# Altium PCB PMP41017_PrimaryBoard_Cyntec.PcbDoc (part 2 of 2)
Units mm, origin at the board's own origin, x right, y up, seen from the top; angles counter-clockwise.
Board outline 81.79 x 50.02 mm, 4 copper layers (Top Layer, Layer 2, Layer 3, Bottom Layer), stack 1.194 mm thick; 52 components, 42 nets, 218 pads, 652 vias.
Unrouted connection lines stored in the file: 2.
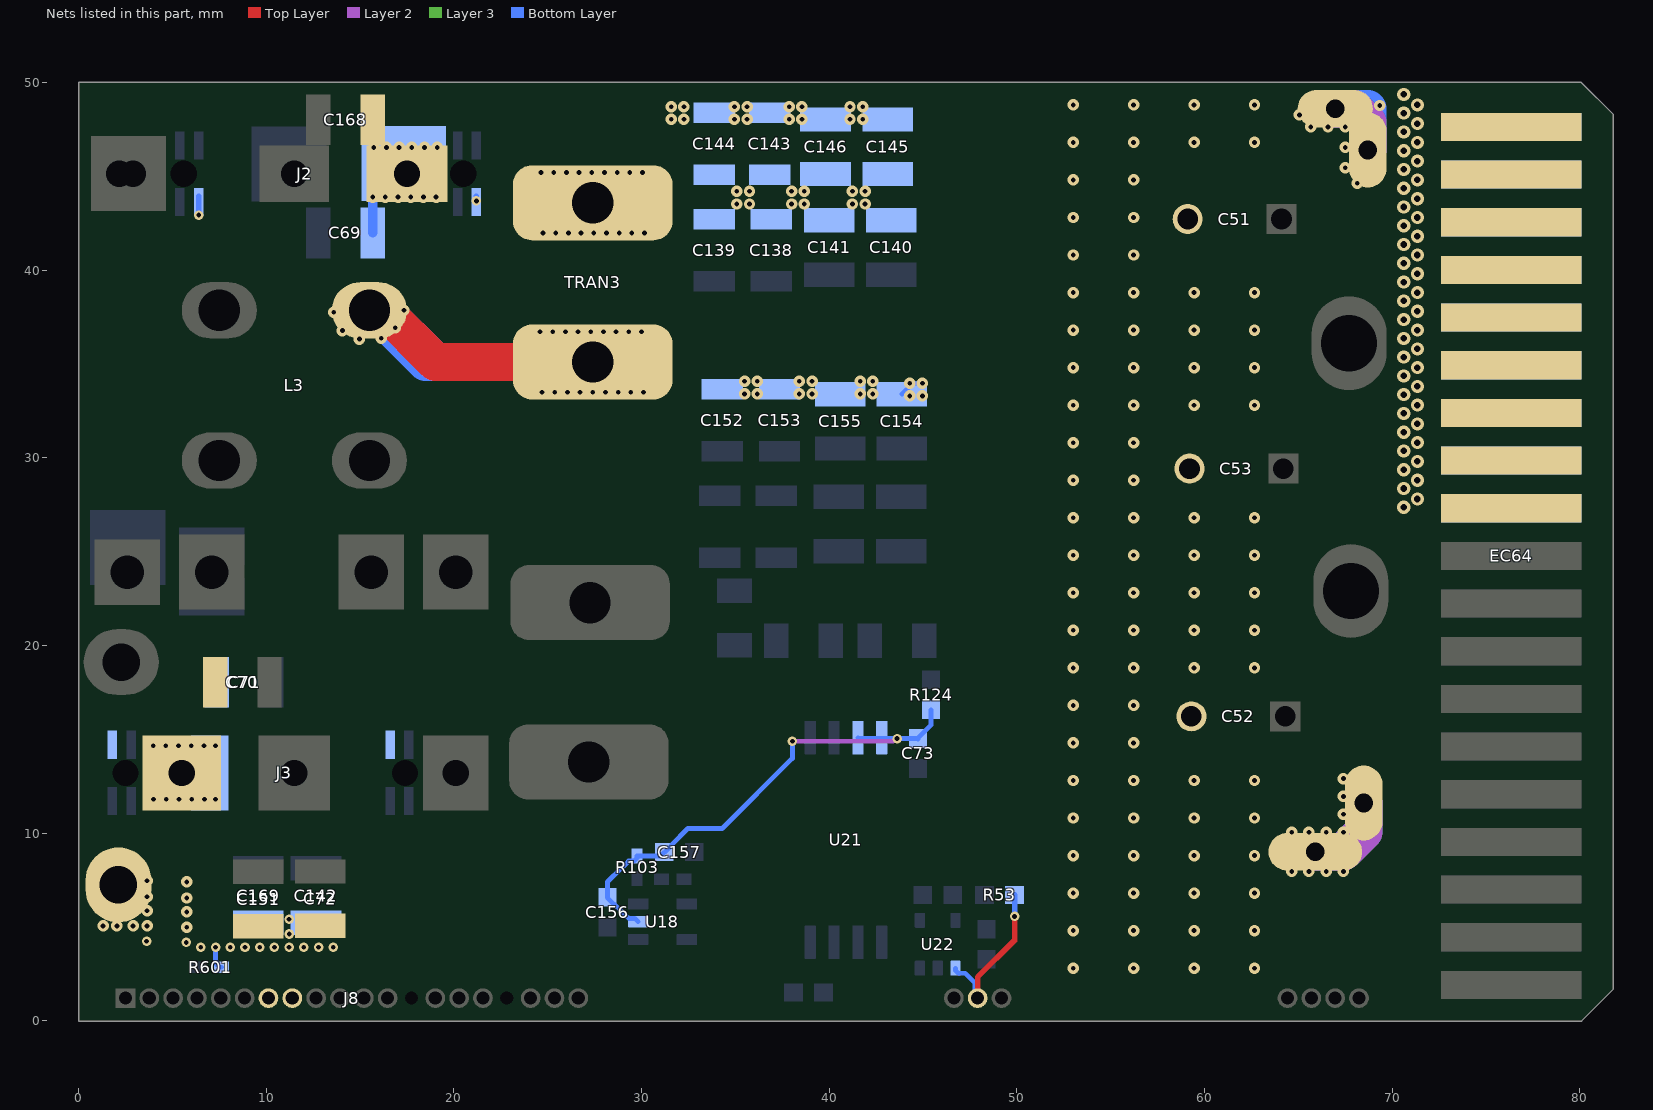
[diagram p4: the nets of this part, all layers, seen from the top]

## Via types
v1: diameter 0.61, hole 0.254, Top Layer to Bottom Layer, tented both sides, 497 vias
v2: diameter 0.7, hole 0.35, Top Layer to Bottom Layer, tented both sides, 110 vias
v3: diameter 0.508, hole 0.254, Top Layer to Bottom Layer, tented both sides, 45 vias

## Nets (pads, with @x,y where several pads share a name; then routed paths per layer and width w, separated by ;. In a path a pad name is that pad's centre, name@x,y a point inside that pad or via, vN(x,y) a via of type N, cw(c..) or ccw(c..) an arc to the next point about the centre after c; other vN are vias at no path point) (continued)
PB_PGND: C69.2 C70.2 C71.2 C72.2 C73.2 C142.2 C143.2 C144.2 C145.2 C146.2 C151.2 C152.2 C153.2 C154.2 C155.2 C156.2 C157.2 C168.2 C169.2 J2.PG J3.PG pad.5@2.126,7.238 pad.5@6.985,13.2 pad.5@17.321,45.681 R103.1 R124.1 R601.1 U18.2 U21.3 U21.4 | length 32.6
  Layer 2 w0.254: v3(38.038,14.891) 43.407,14.891 43.548,15.031 v3(43.616,15.031)
  Bottom Layer w0.254: v3(7.301,3.914) 7.301,3.169 7.351,3.119 7.351,3.019 7.524,2.846 R601.1@7.624,2.846 ; C69.2@15.673,41.978 C69.2@15.674,41.977 ; U18.2@29.815,5.274 29.642,5.447 29.314,5.447 29.167,5.594 29.158,5.594 28.935,5.817 28.935,5.826 28.556,6.205 28.531,6.205 28.183,6.553 C156.2@28.183,6.578 28.183,7.378 ; v3(38.038,14.891) 38.038,13.975 34.304,10.241 32.474,10.241 31.587,9.354 31.587,9.329 31.239,8.981 C157.2@31.214,8.981 31.008,8.776 R103.1@29.759,8.776 29.759,8.676 29.586,8.503 29.307,8.503 28.556,7.751 ; U21.3@41.529,15.082 41.57,15.041 v3@43.616,15.041 ; v3(43.616,15.031) 44.722,15.031 44.737,15.016 C73.2@44.737,15.041 44.737,15.066 45.429,15.758 R124.1@45.429,16.57 ; C154.2@43.873,33.391 44.452,33.969 v1(44.969,33.969) ; 28.183,7.378 28.556,7.751 ; 28.183,7.378 28.183,7.403 28.531,7.751 28.556,7.751
  Bottom Layer w0.5: C69.2@15.673,41.978 v1(15.673,43.885)
  Bottom Layer w2: pad.5@2.126,7.238 pad.5@2.126,7.508
  other v1: 5.77,4.984 1.305,5.05 2.045,5.05 2.903,5.05 3.65,5.05 5.77,5.798 3.65,5.865 5.77,6.539 3.65,6.605 5.77,7.397 3.65,7.463 4,11.798 4.676,11.798 5.352,11.798 6.028,11.798 6.704,11.798 7.295,11.798 3.974,14.65 4.651,14.65 5.327,14.65 6.003,14.65 6.679,14.65 7.295,14.65 44.292,33.293 44.969,33.293 35.489,33.399 36.165,33.399 38.409,33.399 39.085,33.399 41.647,33.399 42.323,33.399 44.292,33.969 35.489,34.075 36.165,34.075 38.409,34.075 39.085,34.075 41.647,34.075 42.323,34.075 16.349,43.885 17.025,43.885 17.701,43.885 18.377,43.885 19.053,43.885 15.728,46.535 16.404,46.535 17.08,46.535 17.757,46.535 18.433,46.535 19.109,46.535 31.582,48.028 32.258,48.028 34.948,48.028 35.625,48.028 37.868,48.028 38.544,48.028 41.107,48.028 41.783,48.028 31.582,48.704 32.258,48.704 34.948,48.704 35.625,48.704 37.868,48.704 38.544,48.704 41.107,48.704 41.783,48.704
  other v3: 6.517,3.914 8.084,3.914 8.868,3.914 9.652,3.914 10.436,3.914 11.22,3.914 12.003,3.914 12.787,3.914 13.571,3.914 5.742,4.168 3.622,4.234 11.232,4.619 11.22,5.403
PB_RX-PFC: J8.8
PB_TX-PFC: J8.7
TEMP_1H_1: J2.5 | length 1
  Bottom Layer w0.3: v3(6.4,42.926) J2.5@6.4,43.933
TEMP_1L_1: J2.1 | length 0.3
  Bottom Layer w0.3: v3(21.2,43.683) J2.1@21.2,43.933
TEMP_2H_1: J3.5
TEMP_2L_1: J3.1
TR1_HV_N: C138.2 C139.2 C140.2 C141.2 C143.1 C144.1 C145.1 C146.1 TRAN3.2 | length 4.2
  Top Layer w2: TRAN3.2@27.4,43.58 TRAN3.2@27.727,43.907
  Layer 2 w2: TRAN3.2@27.4,43.58 TRAN3.2@27.727,43.907
  Layer 3 w2: TRAN3.2@27.4,43.58 TRAN3.2@27.727,43.907
  Bottom Layer w2: TRAN3.2@27.4,43.58 TRAN3.2@30.191,43.58
  other v1: 24.749,41.969 25.425,41.969 26.101,41.969 26.777,41.969 27.454,41.969 28.13,41.969 28.806,41.969 29.482,41.969 30.158,41.969 35.075,43.52 35.752,43.52 37.995,43.52 38.672,43.52 41.234,43.52 41.91,43.52 35.075,44.196 35.752,44.196 37.995,44.196 38.672,44.196 41.234,44.196 41.91,44.196 24.642,45.191 25.318,45.191 25.994,45.191 26.67,45.191 27.346,45.191 28.023,45.191 28.699,45.191 29.375,45.191 30.051,45.191
TR1_HV_P: L3.1 TRAN3.1 | length 37.6
  Top Layer w2: L3.1@15.5,37.852 16.271,37.852 19.023,35.1 TRAN3.1@27.4,35.1
  Layer 2 w2: L3.1@15.5,37.852 16.271,37.852 19.023,35.1 TRAN3.1@27.4,35.1
  Bottom Layer w2: L3.1@16.654,36.941 18.495,35.1 TRAN3.1@27.4,35.1
  other v1: 24.696,33.489 25.372,33.489 26.048,33.489 26.724,33.489 27.4,33.489 28.076,33.489 28.753,33.489 29.429,33.489 30.105,33.489 14.967,36.319 16.128,36.36 24.588,36.711 25.264,36.711 25.94,36.711 26.616,36.711 27.293,36.711 27.969,36.711 28.645,36.711 29.321,36.711 29.997,36.711 14.058,36.774 16.875,36.92 13.6,37.746 17.339,37.852
V0-out: C51.2 C52.2 C53.2 EC64.A1 EC64.A2 EC64.A3 EC64.A4 EC64.A5 EC64.A6 EC64.A7 EC64.A8 EC64.A9 EC64.B1 EC64.B2 EC64.B3 EC64.B4 EC64.B5 EC64.B6 EC64.B7 EC64.B8 EC64.B9 pad.4@65.9,9 pad.4@66.963,48.6 pad.4@68.7,46.4 pad.4@68.481,11.6 | length 16.5
  Layer 2 w2: pad.4@65.9,9 67.4,9 68.481,10.081 pad.4@68.481,11.6 ; pad.4@66.963,48.6 67.963,48.6 68.7,47.863 pad.4@68.7,46.4
  Bottom Layer w2: pad.4@65.9,9 67.4,9 68.481,10.081 pad.4@68.481,11.6 ; pad.4@66.963,48.6 68.7,48.6 pad.4@68.7,46.4
  other v1: 53,2.8 56.22,2.8 59.44,2.8 62.66,2.8 53,4.8 56.22,4.8 59.44,4.8 62.66,4.8 53,6.8 56.22,6.8 59.44,6.8 62.66,6.8 64.643,7.954 65.562,7.954 66.481,7.954 67.4,7.954 53,8.8 56.22,8.8 59.44,8.8 62.66,8.8 64.643,10.046 65.562,10.046 66.481,10.046 67.4,10.046 53,10.8 56.22,10.8 59.44,10.8 62.66,10.8 67.4,10.997 67.4,11.948 53,12.8 56.22,12.8 59.44,12.8 62.66,12.8 67.4,12.899 53,14.8 56.22,14.8 53,16.8 56.22,16.8 53,18.8 56.22,18.8 59.44,18.8 62.66,18.8 53,20.8 56.22,20.8 59.44,20.8 62.66,20.8 53,22.8 56.22,22.8 59.44,22.8 62.66,22.8 53,24.8 56.22,24.8 59.44,24.8 62.66,24.8 53,26.8 56.22,26.8 59.44,26.8 62.66,26.8 53,28.8 56.22,28.8 53,30.8 56.22,30.8 53,32.8 56.22,32.8 59.44,32.8 62.66,32.8 53,34.8 56.22,34.8 59.44,34.8 62.66,34.8 53,36.8 56.22,36.8 59.44,36.8 62.66,36.8 53,38.8 56.22,38.8 59.44,38.8 62.66,38.8 53,40.8 56.22,40.8 53,42.8 56.22,42.8 68.131,44.63 53,44.8 56.22,44.8 67.497,45.447 67.497,46.536 53,46.8 56.22,46.8 59.44,46.8 62.66,46.8 65.659,47.625 66.578,47.625 67.497,47.625 65.054,48.263 69.332,48.768 53,48.8 56.22,48.8 59.44,48.8 62.66,48.8
  other v2: 70.612,27.359 71.341,27.8 70.612,28.359 71.341,28.8 70.612,29.359 71.341,29.8 70.612,30.359 71.341,30.8 70.612,31.359 71.341,31.8 70.612,32.359 71.341,32.8 70.612,33.359 71.341,33.8 70.612,34.359 71.341,34.8 70.612,35.359 71.341,35.8 70.612,36.359 71.341,36.8 70.612,37.359 71.341,37.8 70.612,38.359 71.341,38.8 70.612,39.359 71.341,39.8 70.612,40.359 71.341,40.8 70.612,41.359 71.341,41.8 70.612,42.359 71.341,42.8 70.612,43.359 71.341,43.8 70.612,44.359 71.341,44.8 70.612,45.359 71.341,45.8 70.612,46.359 71.341,46.8 70.612,47.359 71.341,47.8 70.612,48.359 71.341,48.8 70.612,49.359
VPRI: pad.5@47.91,1.2 R53.1 U22.1 | length 8.6
  Top Layer w0.3: pad.5@47.91,1.2 47.91,2.319 49.878,4.287 v3(49.878,5.554)
  Bottom Layer w0.254: U22.1@46.731,2.799 46.731,2.674 46.879,2.526 47.242,2.526 47.758,2.01 47.758,1.352 pad.5@47.91,1.2
  Bottom Layer w0.3: v3(49.878,5.554) R53.1@49.878,6.701
pads on no net: EC64.A19 EC64.B19 J2.0 J3.0 J8.2 J8.3 J8.13 J8.17

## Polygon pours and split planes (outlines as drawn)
no net on Bottom Layer "BOTTOM_LAYER_NONET_P078" (solid, remove dead copper, pour order 78): 42.54,5.077 42.54,3.525 43.659,2.406 47.212,2.406 47.212,5.735 46.963,5.984 43.447,5.984
12Vout on Bottom Layer "Bottom Layer-12Vout" (solid, remove dead copper, pour order 64): 51.816,49.53 51.816,2.794 53.34,1.27 65.435,1.27 70.196,1.27 72.574,3.648 80.088,3.648 80.088,25.514 70.965,25.514 69.43,27.049 69.43,41.817 61.717,49.53
V0-out on Bottom Layer "BOTTOM_LAYER_V0-OUT_P077" (solid, remove dead copper, pour order 77): 63.305,9.714 67.295,13.705 69.518,13.705 69.723,13.5 69.723,9.049 68.032,7.359 64.081,7.359 63.305,8.135
CT2_P on Bottom Layer "BOTTOM_LAYER_CT2_P_P076" (solid, remove dead copper, pour order 76): 18.373,26 31.673,26 31.673,19.836 20.144,19.836 18.373,21.607
CT1_N on Bottom Layer "BOTTOM_LAYER_CT1_N_P067" (solid, remove dead copper, pour order 67): 8.12,35.174 9.775,36.83 9.775,38.662 8.55,39.887 8.534,39.87 5.207,39.87 5.207,35.772 5.805,35.174
V0-out on Bottom Layer "BOTTOM_LAYER_V0-OUT_P059" (solid, remove dead copper, pour order 59): 70.156,41.951 70.156,27.295 70.93,26.522 80.088,26.522 80.088,48.359 72.545,48.359 71.12,49.784 64.516,49.784 64.516,47.654 70.112,42.058
GaN2_SW on Bottom Layer "BOTTOM_LAYER_GAN2_SW_P001" (solid, remove dead copper, pour order 1): 18.669,10.16 27.498,10.16 29.291,11.953 30.755,11.953 31.673,12.87 31.673,16.206 31.115,16.764 23.44,16.764 22.57,15.895 18.373,15.895 18.373,10.456
HVBUS on Bottom Layer "BOTTOM_LAYER_HVBUS_P055" (solid, remove dead copper, pour order 55): 0.011,20.927 4.424,20.927 4.424,18.554 2.983,17.113 0.127,17.113
TR1_HV_P on Bottom Layer "BOTTOM_LAYER_TR1_HV_P_P051" (solid, remove dead copper, pour order 51): 13.247,38.504 14.121,39.378 17.556,39.378 19.473,37.461 30.531,37.461 31.673,36.319 31.673,33.788 30.967,33.083 17.046,33.083 13.247,36.882
TR1_HV_N on Bottom Layer "BOTTOM_LAYER_TR1_HV_N_P031" (solid, remove dead copper, pour order 31): 23.168,45.104 24.022,45.958 44.974,45.958 45.696,45.236 45.696,42.662 44.718,41.684 23.951,41.684 23.16,42.475
HVBUS on Bottom Layer "BOTTOM_LAYER_HVBUS_P045" (solid, remove dead copper, pour order 45): 9.054,49.059 9.652,49.657 13.52,49.657 13.52,43.141 13.172,42.793 9.443,42.793 9.054,43.182
PB_PGND on Bottom Layer "Bottom Layer-PB_GND_D" (solid, remove dead copper, pour order 44): 0.154,5.05 1.923,3.281 14.242,3.281 14.242,5.942 7.405,5.942 6.604,6.743 6.604,9.667 7.93,10.992 7.93,18.923 6.731,18.923 3.683,15.875 3.492,15.684 3.492,10.946 2.313,9.767 0.154,9.767
HVBUS on Bottom Layer "BOTTOM_LAYER_HVBUS_P034" (solid, remove dead copper, pour order 34): 9.578,18.415 10.886,18.415 13.335,15.966 13.335,7.463 9.578,7.463
HVBUS on Bottom Layer "BOTTOM_LAYER_HVBUS_P033" (solid, remove dead copper, pour order 33): 33.581,25.786 45.657,25.786 45.657,23.35 33.746,23.35 33.162,23.935 33.162,25.367
PB_PGND on Bottom Layer "BOTTOM_LAYER_PB_PGND_P032" (solid, remove dead copper, pour order 32): 45.325,32.64 33.127,32.64 33.127,35.076 45.159,35.076 45.743,34.491 45.743,33.059
HVBUS on Bottom Layer "BOTTOM_LAYER_HVBUS_P030" (solid, remove dead copper, pour order 30): 33.058,40.513 45.593,40.513 45.72,40.386 45.72,38.541 45.256,38.077 33.224,38.077 32.639,38.662 32.639,40.094
NetC147_2 on Bottom Layer "BOTTOM_LAYER_NETC147_2_P029" (solid, remove dead copper, pour order 29): 13.579,30.689 14.654,31.764 44.509,31.764 45.642,30.63 45.642,27.825 44.869,27.051 15.315,27.051 13.535,28.831
PB_PGND on Bottom Layer "BOTTOM_LAYER_PB_PGND_P024" (solid, remove dead copper, pour order 24): 32.258,49.657 44.831,49.657 45.72,48.768 45.72,47.117 20.101,47.117 16.107,43.123 15,43.123 15,49.657
CT1_P on Bottom Layer "BOTTOM_LAYER_CT1_P_P005" (solid, remove dead copper, pour order 5): 0.127,47.879 0.127,22.88 0.762,22.245 4.211,22.245 4.699,22.733 4.699,48.26 0.508,48.26
PB_PGND on Top Layer "TOP_LAYER_PB_PGND_P075" (solid, remove dead copper, pour order 75): 32.258,49.657 44.831,49.657 45.72,48.768 45.72,47.117 20.101,47.117 16.107,43.123 15,43.123 15,49.657
HVBUS on Top Layer "TOP_LAYER_HVBUS_P074" (solid, remove dead copper, pour order 74): 33.581,25.786 45.657,25.786 45.657,23.35 33.746,23.35 33.162,23.935 33.162,25.367
PB_PGND on Top Layer "TOP_LAYER_PB_PGND_P073" (solid, remove dead copper, pour order 73): 45.325,32.64 33.127,32.64 33.127,35.076 45.159,35.076 45.743,34.491 45.743,33.059
HVBUS on Top Layer "TOP_LAYER_HVBUS_P072" (solid, remove dead copper, pour order 72): 33.058,40.513 45.593,40.513 45.72,40.386 45.72,38.541 45.256,38.077 33.224,38.077 32.639,38.662 32.639,40.094
CT1_N on Top Layer "TOP_LAYER_CT1_N_P068" (solid, remove dead copper, pour order 68): 5.207,39.87 8.715,39.87 9.775,38.809 9.775,36.83 8.548,35.603 5.376,35.603 5.207,35.772
V0-out on Top Layer "Top Layer-V0-out" (solid, remove dead copper, pour order 62): 51.816,49.784 51.816,2.794 53.34,1.27 68.58,1.27 69.618,2.308 69.618,13.68 64.624,18.674 64.624,25.046 66.099,26.522 80.088,26.522 80.088,48.359 72.545,48.359 71.12,49.784 65.024,49.784
12Vout on Top Layer "TOP_LAYER_12VOUT_P061" (solid, remove dead copper, pour order 61): 70.062,3.706 70.062,14.368 65.435,18.995 65.435,24.604 66.617,25.786 71.256,25.786 71.529,25.514 80.088,25.514 80.088,3.648 72.574,3.648 72.314,3.388 70.38,3.388
GaN2_SW on Top Layer "TOP_LAYER_GAN2_SW_P057" (solid, remove dead copper, pour order 57): 18.373,10.456 18.373,15.895 22.57,15.895 23.44,16.764 31.115,16.764 31.673,16.206 31.673,11.673 30.16,10.16 18.669,10.16
HVBUS on Top Layer "TOP_LAYER_HVBUS_P054" (solid, remove dead copper, pour order 54): 0.011,20.927 4.424,20.927 4.424,18.554 2.983,17.113 0.127,17.113
CT1_N on Top Layer "TOP_LAYER_CT1_N_P053" (solid, remove dead copper, pour order 53): 5.327,27.012 5.747,27.432 8.146,27.432 9.578,26 9.578,22.297 9.125,21.844 5.327,21.844
TR1_HV_P on Top Layer "TOP_LAYER_TR1_HV_P_P052" (solid, remove dead copper, pour order 52): 13.247,39.368 13.749,39.87 17.064,39.87 19.473,37.461 30.808,37.461 31.673,36.596 31.673,33.788 30.967,33.083 17.046,33.083 13.247,36.882
NetC147_2 on Top Layer "TOP_LAYER_NETC147_2_P028" (solid, remove dead copper, pour order 28): 13.579,30.689 14.654,31.764 44.509,31.764 45.642,30.63 45.642,27.825 44.869,27.051 15.154,27.051 13.531,28.674
PB_PGND on Top Layer "TOP_LAYER_PB_PGND_P046" (solid, remove dead copper, pour order 46): 15,49.657 18.521,49.657 19.668,48.51 19.668,41.684 15.011,41.684
TR1_HV_N on Top Layer "TOP_LAYER_TR1_HV_N_P041" (solid, remove dead copper, pour order 41): 22.912,44.502 24.205,45.795 44.81,45.795 45.429,45.175 45.429,42.396 44.554,41.52 23.787,41.52 22.906,42.402
PB_PGND on Top Layer "Top Layer-PB_GND_D" (solid, remove dead copper, pour order 39): 0.154,5.612 2.484,3.281 14.65,3.281 14.65,5.713 6.907,5.713 6.604,6.016 6.604,9.667 7.93,10.992 7.93,18.923 6.731,18.923 3.683,15.875 3.302,15.494 3.302,10.756 2.313,9.767 0.154,9.767
HVBUS on Top Layer "TOP_LAYER_HVBUS_P035" (solid, remove dead copper, pour order 35): 9.578,18.653 10.648,18.653 13.335,15.966 13.335,7.293 9.578,7.293
CT1_P on Top Layer "TOP_LAYER_CT1_P_P009" (solid, remove dead copper, pour order 9): 0.127,47.879 0.127,22.47 0.489,22.107 4.301,22.107 4.699,22.505 4.699,48.26 0.508,48.26
HVBUS on Top Layer "TOP_LAYER_HVBUS_P007" (solid, remove dead copper, pour order 7): 9.054,49.657 9.054,41.684 13.832,41.684 13.832,49.657
V0-out on Layer 3 "LAYER_3_V0-OUT_P048" (solid, remove dead copper, pour order 48): 52.197,49.784 78.74,49.784 80.088,48.436 80.088,2.54 78.818,1.27 53.34,1.27 52.197,2.413
PB_PGND on Layer 3 "LAYER_3_PB_PGND_P022" (solid, remove dead copper, pour order 22): 11.959,18.653 11.959,25.635 19.185,25.635 19.185,39.721 18.812,40.094 13.813,40.094 13.813,49.657 44.831,49.657 46.99,47.498 46.99,13.73 35.8,2.54 2.808,2.54 0,5.348 0.078,16.3 9.606,16.3
CT1_N on Layer 3 "LAYER_3_CT1_N_P010" (solid, remove dead copper, pour order 10): 0.519,35.726 0.519,21.844 9.125,21.844 9.652,22.371 9.652,27.716 6.414,27.716 5.08,29.049 5.08,32.135 8.548,35.603 9.775,36.83 9.775,38.662 8.55,39.887 4.68,39.887
12Vout on Layer 2 "Layer 2-12Vout" (solid, remove dead copper, pour order 66): 51.816,2.794 53.34,1.27 78.558,1.27 80.088,2.8 80.088,26.522 70.148,26.521 69.723,26.946 69.723,41.975 64.1,47.598 64.1,49.751 61.948,49.75 51.816,49.75
V0-out on Layer 2 "LAYER_2_V0-OUT_P060" (solid, remove dead copper, pour order 60): 64.516,47.783 70.112,42.187 70.156,42.08 70.156,27.015 80.088,27.015 80.088,48.359 78.663,49.784 64.581,49.784 64.516,49.719
HVBUS on Layer 2 "Layer 2-HVBUS" (solid, remove dead copper, pour order 27): 15.093,42.545 25.744,42.545 26.87,41.418 26.943,41.388 45.696,41.388 45.72,41.364 46.99,40.094 46.99,17.907 45.593,16.51 15.416,16.51 14.002,15.097 14.002,10.643 13.52,10.16 10.12,10.16 9.339,10.941 9.339,15.279 8.108,16.51 0.73,16.51 0.127,17.113 0.127,20.193 1.27,21.336 29.241,21.336 30.861,22.956 30.861,36.937 30.206,37.592 13.146,37.592 9.054,41.684 9.054,49.657 14.224,49.657 14.224,43.414
PB_PGND on Layer 2 "LAYER_2_PB_PGND_P018" (solid, remove dead copper, pour order 18): 0.834,4.931 2.706,3.06 14.058,3.06 14.058,8.793 9.628,8.793 7.85,10.55 7.85,15.668 7.643,15.875 3.683,15.875 3.302,15.494 3.302,10.756 2.706,10.16 0.834,10.16
TR1_HV_N on Layer 2 "LAYER_2_TR1_HV_N_P042" (solid, remove dead copper, pour order 42): 23.315,44.905 24.205,45.795 45.335,45.795 45.335,41.52 23.787,41.52 23.306,42.001
PB_PGND on Layer 2 "LAYER_2_PB_PGND_P021" (solid, remove dead copper, pour order 21): 15.093,49.383 15.367,49.657 44.831,49.657 45.593,48.895 45.593,45.958 15.093,45.958
CT1_N on Layer 2 "LAYER_2_CT1_N_P014" (solid, remove dead copper, pour order 14): 0.519,35.628 0.519,21.844 8.602,21.844 9.054,22.295 9.054,27.051 7.078,27.051 5.479,28.65 5.479,32.941 9.775,37.237 9.775,38.662 8.55,39.887 4.778,39.887

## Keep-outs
Keep-Out Layer:
  text ".Layer_Name" at -20.343,-59.464 h1.52

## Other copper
Top Layer:
  rectangle net PB_PGND: 7.267,11.182 7.879,16
  rectangle net 12Vout: 72.574,3.648 80.097,25.479
  rectangle net V0-out: 72.583,26.522 80.095,48.343
  rectangle net GaN2_SW: 21.55,10.357 23.44,15.684
  text ".Layer_Name" at -20.343,-59.464 h1.52
Layer 2:
  rectangle net CT1_P: 0.281,21.844 3.937,26.225
  rectangle net CT1_P: 0.281,42.229 4.604,48.069
  pour cut-out: 19.705,47.061 cw(c20.205,47.061) 20.705,47.061 cw(c20.205,47.061)
Layer 3:
  rectangle net TEMP_1H_1: 6.075,42.333 7.1,43.907
  rectangle net TEMP_1L_1: 20.619,43.275 22,44.184
  rectangle net CT1_P: 0.281,21.844 3.937,26.225
Bottom Layer:
  rectangle net V0-out: 72.583,26.522 80.095,48.343
  rectangle net 12Vout: 72.574,3.648 80.097,25.479
  rectangle net GaN2_SW: 21.55,10.652 23.44,15.684
  rectangle net TEMP_2H_1: 15.416,14.272 16.858,16.51
  rectangle net TEMP_2L_1: 0.445,14.272 2.1,15.78
  pour cut-out: 19.693,47.063 cw(c20.193,47.063) 20.693,47.063 cw(c20.193,47.063)
  text ".Layer_Name" at -20.343,-59.464 h1.52

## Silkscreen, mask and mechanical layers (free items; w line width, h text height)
Top Overlay:
  lines w0.2: 0.005,0 0.005,3.273 32.005,3.273 32.005,0 0.005,0
  text "'.PRJ_Number'.PCB_Rev" at 116.739,-34.38 h2.75
  text ".Layer_Name" at -20.343,-59.464 h1.52
Bottom Overlay:
  text ".Layer_Name" at -20.343,-59.464 h1.52
Top Paste:
  text ".Layer_Name" at -20.343,-59.464 h1.52
Bottom Paste:
  text ".Layer_Name" at -20.343,-59.464 h1.52
Top Solder:
  text ".Layer_Name" at -20.343,-59.464 h1.52
  text ".Layer_Name" at -20.343,-59.464 h1.52
Bottom Solder:
  text ".Layer_Name" at -20.343,-59.464 h1.52
Drill Guide:
  text ".Layer_Name" at -20.343,-59.464 h1.52
M1 Board Outline:
  lines w0.1: 70,50 0,50 0,0 0,-0.017 80.088,-0.017 81.788,1.683 81.788,48.283 80.071,50 70.005,50
  text ".Layer_Name" at -20.343,-59.464 h1.52
M2 Board Dimensions:
  rectangle: -34.999,-44.643 -31.824,-41.468
  rectangle: -31.824,-47.818 -22.299,-44.643
  lines w0.178: -34.999,-44.643 -9.599,-44.643 ; -31.824,-47.818 -31.824,-41.468 ; -28.649,-47.818 -28.649,-41.468 ; -22.299,-47.818 -22.299,-41.468 ; -15.949,-47.818 -15.949,-41.468 ; -34.999,-47.818 -9.599,-47.818 -9.599,-41.468 -34.999,-41.468 -34.999,-47.818
  text ".Layer_Name" at -20.343,-59.464 h1.52
M3 3D STEP Top:
  text ".Layer_Name" at -20.343,-59.464 h1.52
M4 3D STEP Bottom:
  text ".Layer_Name" at -20.343,-59.464 h1.52
M5 Assembly Top:
  lines w0.254: -42.416,-61.285 125.224,-61.285 ; -42.416,-56.12 125.275,-56.12 ; -42.416,-50.955 -42.416,-66.449 59.311,-66.449 125.275,-66.449 125.275,-50.955 -42.403,-50.955 -42.403,-66.449 -2.386,-66.449 ; 20.195,-66.449 20.195,-50.955 ; 52.377,-56.12 52.377,-50.955 ; 73.713,-56.12 73.713,-50.955 ; 89.512,-66.614 89.512,-61.463
  text "COMPONENTS MARKED 'DNP' SHOULD NOT BE POPULATED." at -5.7,-45.748 h1.52
  text "ASSEMBLY VARIANT:" at -5.713,-48.682 h1.52
  text ".VariantName" at 20.601,-48.682 h1.52
  text "PCB VIEWED FROM TOP SIDE" at -40.803,-54.312 h1.52
  text "BOARD #:" at 22.1,-54.312 h1.52
  text ".PRJ_Number" at 35.956,-54.312 h1.52
  text "REV:" at 57.406,-54.312 h1.52
  text ".PCB_Rev" at 64.81,-54.312 h1.52
  text "SVN REV:" at 78.691,-54.312 h1.52
  text ".VersionControl_RevNumber" at 91.544,-54.312 h1.52
  text "TID #:" at 22.1,-59.477 h1.52
  text ".TID" at 35.956,-59.477 h1.52
  text "PLOT NAME =" at -40.803,-64.693 h1.52
  text ".plot_File_Name" at -20.343,-64.693 h1.52
  text "GENERATED    :" at 22.151,-64.693 h1.52
  text ".Print_Date" at 44.236,-64.693 h1.52
  text ".Print_Time" at 62.753,-64.693 h1.52
  text "TEXAS INSTRUMENTS" at 94.871,-64.693 h1.52
M6 Assembly Bottom:
  lines w0.254: -42.429,-56.133 125.262,-56.133 ; -42.378,-61.297 125.262,-61.297 ; -6.665,-66.627 -6.665,-61.475 ; 9.133,-56.133 9.133,-50.968 ; 30.469,-56.133 30.469,-50.968 ; 62.651,-66.462 62.651,-50.968 ; 85.232,-66.462 125.249,-66.462 125.249,-50.968 -42.429,-50.968 -42.429,-66.462 23.535,-66.462 125.262,-66.462 125.262,-50.968
  text "COMPONENTS MARKED 'DNP' SHOULD NOT BE POPULATED." at 119.992,-45.736 h1.52
  text ".VariantName" at 93.474,-48.682 h1.52
  text "ASSEMBLY VARIANT:" at 119.865,-48.682 h1.52
  text ".VersionControl_RevNumber" at -8.697,-54.325 h1.52
  text "SVN REV:" at 4.155,-54.325 h1.52
  text ".PCB_Rev" at 18.036,-54.325 h1.52
  text "REV:" at 25.44,-54.325 h1.52
  text ".PRJ_Number" at 46.89,-54.325 h1.52
  text "BOARD #:" at 60.746,-54.325 h1.52
  text "PCB VIEWED FROM BOTTOM SIDE" at 123.649,-54.325 h1.52
  text ".TID" at 46.89,-59.49 h1.52
  text "TID #:" at 60.746,-59.49 h1.52
  text "TEXAS INSTRUMENTS" at -12.025,-64.705 h1.52
  text ".Print_Time" at 20.093,-64.705 h1.52
  text ".Print_Date" at 38.61,-64.705 h1.52
  text "GENERATED    :" at 60.695,-64.705 h1.52
  text ".plot_File_Name" at 103.19,-64.705 h1.52
  text "PLOT NAME =" at 123.649,-64.705 h1.52
M9 Title Sheet:
  drawing of 57 lines, arcs and shapes, not listed
  text "1" at -16.207,166.469 h1.78
  text "2" at 47.183,166.469 h1.78
  text "3" at 110.412,166.469 h1.78
  text "4" at 174.081,166.469 h1.78
  text "5" at 237.556,166.469 h1.78
  text "6" at 301.183,166.469 h1.78
  text "A" at -45.578,137.436 h1.78
  text "A" at 330.342,137.436 h1.78
  text "B" at -45.578,76.984 h1.78
  text "B" at 330.342,76.984 h1.78
  text "C" at -45.578,16.659 h1.78
  text "C" at 330.342,16.659 h1.78
  text "PROJECT TITLE:" at 253.126,-30.61 h1.14
  text ".PRJ_Title" at 254.396,-33.996 h1.78
  text "DESIGNED FOR:" at 253.126,-38.255 h1.14
  text ".PRJ_Customer" at 254.396,-41.811 h1.78
  text "D" at -45.578,-43.539 h1.78
  text "D" at 330.342,-43.539 h1.78
  text "FILE NAME:" at 253.126,-45.875 h1.14
  text ".PCB_File_Name_No_Path" at 254.396,-48.923 h1.78
  text "Texas Instruments (TI) and/or its licensors do not warrant the accuracy or completeness of this specification" at 126.9,-53.034 h1.14
  text "ENGINEER:" at 253.126,-53.241 h1.14
  text "LAYOUT BY:" at 291.353,-53.241 h1.14
  text "or any information contained therein. TI and/or its licensors do not warrant that this design will meet" at 125.758,-55.896 h1.14
  text ".PRJ_Engineer" at 254.396,-57.178 h1.78
  text ".PCB_Layout" at 292.635,-57.178 h1.78
  text "the specifications, will be suitable for your application or fit for any particular purpose, or will operate in" at 125.758,-58.757 h1.14
  text ".Layer_Name" at -20.343,-59.464 h1.52
  text "ALTIUM DESIGNER VERSION:" at 291.353,-61.115 h1.14
  text "an implementation. TI and/or its licensors do not warrant that the design is production worthy. You should" at 125.758,-61.619 h1.14
  text "completely validate and test your design implementation to confirm the system functionality for your application." at 126.9,-64.481 h1.14
  text ".print_Scale" at 254.396,-64.502 h1.78
  text ".Application_BuildNumber" at 292.635,-64.502 h1.78
  text "1" at -16.207,-69.751 h1.78
  text "2" at 47.183,-69.751 h1.78
  text "3" at 110.412,-69.751 h1.78
  text "4" at 174.081,-69.751 h1.78
  text "5" at 237.556,-69.751 h1.78
  text "6" at 301.183,-69.751 h1.78
M10 Fab Notes:
  drawing of 189 lines, arcs and shapes, not listed
  text "DESIGN INFORMATION" at 279.504,123.788 h1.52
  text "MIN. TRACK WIDTH:" at 263.132,120.432 h1.52
  text "8" at 290.977,120.432 h1.52
  text "MIL" at 294.908,120.432 h1.52
  text "7.874" at 286.751,117.342 h1.52
  text "MIN. CLEARANCE:" at 263.132,117.28 h1.52
  text "MIL" at 294.908,117.28 h1.52
  text "MIN. VIA PAD SIZE:" at 263.132,114.127 h1.52
  text "24" at 290.215,114.127 h1.52
  text "MIL" at 294.908,114.127 h1.52
  text "0.05mm (2MIL)" at 280.785,110.827 h1.52
  text "MINIMUM ANNULAR RING" at 254.77,110.618 h1.52
  text "EXTERNAL" at 298.769,110.618 h1.52
  text "PER" at 259.85,107.821 h1.52
  text "IPC-D-275 CLASS 2 LEVEL C" at 265.438,107.821 h1.52
  text "MIL, HOLES" at 303.239,105.269 h1.52
  text "+/-" at 293.27,105.051 h1.52
  text "+/-" at 314.962,105.051 h1.52
  text "REGISTRATION TOLERANCES:" at 254.77,105.024 h1.52
  text "METAL" at 285.244,105.024 h1.52
  text "5" at 299.88,105.024 h1.52
  text "3" at 321.038,105.024 h1.52
  text "MIL" at 323.991,105.024 h1.52
  text "HOLE SIZE TOLERANCE (UNLESS OTHERWISE SPECIFIED):" at 254.77,102.527 h1.52
  text "+/-" at 314.962,102.454 h1.52
  text "3" at 321.038,102.427 h1.52
  text "MIL" at 323.991,102.427 h1.52
  text "MATERIAL:" at 252.871,98.931 h1.52
  text "FR-4 High Tg" at 277.926,95.666 h1.52
  text "X" at 274.258,95.463 h1.52
  text "FR-408" at 263.564,95.348 h1.52
  text "OTHER" at 301.359,95.348 h1.52
  text "62 MIL (1.6mm) +/-10%" at 271.695,91.715 h1.52
  text "X" at 268.644,91.653 h1.52
  text "THICKNESS:" at 254.77,91.507 h1.52
  text "OTHER" at 304.331,91.507 h1.52
  text "TOLERANCE:" at 254.77,87.993 h1.52
  text "X" at 276.315,87.993 h1.52
  text "ANSI IPC-6012 TYPE 3 CLASS 2" at 280.837,87.993 h1.52
  text "OTHER +/-" at 280.836,84.331 h1.52
  text "BOW & TWIST:" at 254.77,80.643 h1.52
  text "X" at 276.315,80.643 h1.52
  text "ANSI IPC-6012 TYPE 3 CLASS 2" at 280.837,80.643 h1.52
  text "OTHER +/-" at 280.836,76.917 h1.52
  text "DRILLING:" at 252.871,73.599 h1.52
  text "NC_DRILL FILES" at 297.6,70.928 h1.52
  text "REFERENCE:" at 254.77,70.828 h1.52
  text "X" at 271.464,70.825 h1.52
  text "AS SHOWN" at 275.985,70.828 h1.52
  text "X" at 294.349,70.828 h1.52
  text "OTHER" at 305.169,67.214 h1.52
  text "PTH COPPER THICKNESS:" at 254.762,67.125 h1.52
  text "X" at 283.698,67.125 h1.52
  text "20-30 um" at 286.949,67.125 h1.52
  text "BOARD FINISH:" at 252.871,63.376 h1.52
  text "SILKSCREEN:" at 256.813,60.579 h1.52
  text "X" at 281.141,60.579 h1.52
  text "TOP" at 284.113,60.579 h1.52
  text "X" at 294.095,60.579 h1.52
  text "BOTTOM" at 297.092,60.579 h1.52
  text "SILKSCREEN COLOR:" at 256.813,56.637 h1.52
  text "X" at 281.116,56.637 h1.52
  text "WHITE" at 284.113,56.637 h1.52
  text "OTHER" at 297.092,56.637 h1.52
  text "X" at 284.443,52.993 h1.52
  text "GREEN" at 287.44,52.993 h1.52
  text "OTHER" at 303.137,52.993 h1.52
  text "SOLDER RESIST COLOR:" at 256.813,52.819 h1.52
  text "X" at 284.443,49.075 h1.52
  text "MATTE" at 287.44,49.075 h1.52
  text "SEMI-GLOSS" at 303.126,49.059 h1.52
  text "IMMERSION GOLD (ENIG)" at 279.82,44.687 h1.52
  text "ENEPIG" at 313.794,44.503 h1.52
  text "SURFACE FINISH:" at 252.871,44.478 h1.52
  text "X" at 275.299,44.478 h1.52
  text "IMM. TIN/SILVER OR EQUIV" at 261.241,40.99 h1.52
  text "OTHER" at 297.6,40.89 h1.52
  text "ARRAY/PANEL:" at 252.871,36.944 h1.52
  text "CUT AND TRIM PER M1 BOARD OUTLINE" at 279.82,36.735 h1.52
  text "N.C. ROUTE" at 279.82,33.281 h1.52
  text "X" at 297.295,33.281 h1.52
  text "V. SCORE" at 301.817,33.281 h1.52
  text "CERTIFICATION:" at 252.871,30.001 h1.52
  text "MATERIALS AND WORKMANSHIP FOR ALL PCBS" at 271.286,30.001 h1.52
  text "TO MEET OR EXCEED THE REQUIREMENTS OF:" at 271.286,27.612 h1.52
  text "X" at 262.078,24.345 h1.52
  text "ANSI IPC-A-600F CLASS ->" at 265.33,24.345 h1.52
  text "X" at 307.189,24.345 h1.52
  text "2" at 309.983,24.345 h1.52
  text "1" at 301.982,24.307 h1.52
  text "3" at 318.974,24.307 h1.52
  text "X" at 282.703,20.594 h1.52
  text "RoHS" at 285.954,20.594 h1.52
  text "OTHER" at 302.322,20.594 h1.52
  text "PER ORDER" at 312.407,20.594 h1.52
  text "ALL BOARDS MUST MEET OR EXCEED UL94-V0 REQUIREMENTS." at 253.57,16.687 h1.52
  text "PCB MUST BEAR THE UL94V-0 UL REGISTERED MATERIAL ID NUMBER" at 253.57,13.739 h1.52
  text "ADDITIONAL REQUIREMENTS:" at 252.871,9.435 h1.52
  text "MICROSECTION:" at 254.77,6.714 h1.52
  text "YES" at 277.776,6.714 h1.52
  text "REQUIRED" at 299.658,3.048 h1.52
  text "BARE BOARD ELEC. TEST:" at 254.77,2.976 h1.52
  text "NONE" at 287.936,2.976 h1.52
  text "X" at 296.66,2.976 h1.52
  text "PER ORDER" at 314.694,2.976 h1.52
  text "XX MIL VIAS REQUIRE NON-CONDUCTIVE FILL AND PLANARIZE" at 259.041,-2.23 h1.5
  text "XX MIL VIAS REQUIRE CONDUCTIVE FILL AND PLANARIZE" at 259.244,-4.871 h1.52
  text "OUTER XX MIL TRACES REQUIRE 50 OHM SINGLE-ENDED IMPEDANCE" at 259.219,-9.021 h1.47
  text "LAYER 2 & 3 (INNER LAYERS) XX MIL WIDE, XX MIL SPACE / TRACES REQUIRE 100 OHM DIFFERENTIAL IMPEDANCE" at 259.016,-15.008 h1.52
  text ".Layer_Name" at -20.343,-59.464 h1.52
M11 Gerber Information:
  lines w0.254: -42.416,-61.285 125.224,-61.285 ; -42.416,-56.12 125.275,-56.12 ; -42.416,-50.955 -42.416,-66.449 59.311,-66.449 125.275,-66.449 125.275,-50.955 -42.403,-50.955 -42.403,-66.449 -2.386,-66.449 ; 20.195,-66.449 20.195,-50.955 ; 52.377,-56.12 52.377,-50.955 ; 73.713,-56.12 73.713,-50.955 ; 89.512,-66.614 89.512,-61.463
  text "ALL ARTWORK VIEWED FROM TOP SIDE" at -40.803,-54.312 h1.52
  text "BOARD #:" at 22.1,-54.312 h1.52
  text ".PRJ_Number" at 35.956,-54.312 h1.52
  text "REV:" at 57.406,-54.312 h1.52
  text ".PCB_Rev" at 64.81,-54.312 h1.52
  text "SVN REV:" at 78.691,-54.312 h1.52
  text ".VersionControl_RevNumber" at 91.544,-54.312 h1.52
  text "LAYER NAME =" at -40.803,-59.464 h1.52
  text "TID #:" at 22.1,-59.477 h1.52
  text ".TID" at 35.956,-59.477 h1.52
  text "PLOT NAME =" at -40.803,-64.693 h1.52
  text ".plot_File_Name" at -20.343,-64.693 h1.52
  text "GENERATED    :" at 22.151,-64.693 h1.52
  text ".Print_Date" at 44.236,-64.693 h1.52
  text ".Print_Time" at 62.753,-64.693 h1.52
  text "TEXAS INSTRUMENTS" at 94.871,-64.693 h1.52
M12 Stackup:
  drawing of 341 lines, arcs and shapes, not listed
  text "Layer" at 214.469,162.365 h1.52
  text "Name" at 224.881,162.365 h1.52
  text "Material" at 248.497,162.365 h1.52
  text "Thickness" at 270.335,162.365 h1.52
  text "Constant" at 286.841,162.365 h1.52
  text "Board Layer Stack" at 301.315,162.365 h1.52
  text "Top Overlay" at 224.881,159.317 h1.52
  text "Top Solder" at 224.881,156.269 h1.52
  text "Solder Resist" at 248.497,156.269 h1.52
  text "0.40mil" at 270.335,156.269 h1.52
  text "3.5" at 286.841,156.269 h1.52
  text "1" at 214.469,153.221 h1.52
  text "Top Layer" at 224.881,153.221 h1.52
  text "CF-005" at 248.497,153.221 h1.52
  text "2.76mil" at 270.335,153.221 h1.52
  text "Dielectric 1" at 224.881,150.173 h1.52
  text "PP-022" at 248.497,150.173 h1.52
  text "12.00mil" at 270.335,150.173 h1.52
  text "4.5" at 286.841,150.173 h1.52
  text "2" at 214.469,147.125 h1.52
  text "Layer 2" at 224.881,147.125 h1.52
  text "CF-005" at 248.497,147.125 h1.52
  text "2.76mil" at 270.335,147.125 h1.52
  text "Dielectric3" at 224.881,144.077 h1.52
  text "Core-029" at 248.497,144.077 h1.52
  text "12.00mil" at 270.335,144.077 h1.52
  text "4.7" at 286.841,144.077 h1.52
  text "3" at 214.469,141.029 h1.52
  text "Layer 3" at 224.881,141.029 h1.52
  text "CF-005" at 248.497,141.029 h1.52
  text "2.76mil" at 270.335,141.029 h1.52
  text "Dielectric 5" at 224.881,137.981 h1.52
  text "PP-022" at 248.497,137.981 h1.52
  text "12.00mil" at 270.335,137.981 h1.52
  text "4.5" at 286.841,137.981 h1.52
  text "4" at 214.469,134.933 h1.52
  text "Bottom Layer" at 224.881,134.933 h1.52
  text "CF-005" at 248.497,134.933 h1.52
  text "2.76mil" at 270.335,134.933 h1.52
  text "Bottom Solder" at 224.881,131.885 h1.52
  text "Solder Resist" at 248.497,131.885 h1.52
  text "0.40mil" at 270.335,131.885 h1.52
  text "3.5" at 286.841,131.885 h1.52
  text "Bottom Overlay" at 224.881,128.837 h1.52
  text "GaN Board1" at 6.652,47.652 h0.89
  text "Transformer1" at 34.152,38.852 h0.89
  text "Resonant Choke 1&2" at 3.652,33.652 h0.89
  text "Board_CST" at 6.752,20.301 h0.89
  text "Transformer2" at 33.322,17.718 h0.89
  text "GaN Board2" at 7.352,13.952 h0.89
  text "Flyback" at 2.002,3.849 h0.89
  text "McU Board" at 49.452,2.352 h0.89
  text ".Layer_Name" at -20.343,-59.464 h1.52
M13 Component Bodies Top:
  text ".Layer_Name" at -20.343,-59.464 h1.52
M14 Component Bodies Bottom:
  text ".Layer_Name" at -20.343,-59.464 h1.52
M15 Courtyards Top:
  text ".Layer_Name" at -20.343,-59.464 h1.52
M16 Courtyards Bottom:
  text ".Layer_Name" at -20.343,-59.464 h1.52
Drill Drawing:
  drawing of 177 lines, arcs and shapes, not listed
  text "Symbol" at 107.637,47.524 h1.83
  text "Quantity" at 115.271,47.524 h1.83
  text "Finished Hole Size" at 123.704,47.524 h1.83
  text "Plated" at 139.873,47.524 h1.83
  text "Hole Type" at 146.455,47.524 h1.83
  text "Drill Layer Pair" at 155.984,47.524 h1.83
  text "Hole Tolerance" at 174.382,47.524 h1.83
  text "2" at 115.271,44.366 h1.52
  text "27.56mil (0.700mm)" at 123.704,44.366 h1.52
  text "NPTH" at 139.873,44.366 h1.52
  text "Round" at 146.455,44.366 h1.52
  text "Top Layer - Bottom Layer" at 155.984,44.366 h1.52
  text "542" at 115.271,41.208 h1.52
  text "10.00mil (0.254mm)" at 123.704,41.208 h1.52
  text "PTH" at 139.873,41.208 h1.52
  text "Round" at 146.455,41.208 h1.52
  text "Top Layer - Bottom Layer" at 155.984,41.208 h1.52
  text "110" at 115.271,38.051 h1.52
  text "13.78mil (0.350mm)" at 123.704,38.051 h1.52
  text "PTH" at 139.873,38.051 h1.52
  text "Round" at 146.455,38.051 h1.52
  text "Top Layer - Bottom Layer" at 155.984,38.051 h1.52
  text "25" at 115.271,34.893 h1.52
  text "27.56mil (0.700mm)" at 123.704,34.893 h1.52
  text "PTH" at 139.873,34.893 h1.52
  text "Round" at 146.455,34.893 h1.52
  text "Top Layer - Bottom Layer" at 155.984,34.893 h1.52
  text "6" at 115.271,31.735 h1.52
  text "43.31mil (1.100mm)" at 123.704,31.735 h1.52
  text "PTH" at 139.873,31.735 h1.52
  text "Round" at 146.455,31.735 h1.52
  text "Top Layer - Bottom Layer" at 155.984,31.735 h1.52
  text "2" at 115.271,28.577 h1.52
  text "78.74mil (2.000mm)" at 123.704,28.577 h1.52
  text "PTH" at 139.873,28.577 h1.52
  text "Round" at 146.455,28.577 h1.52
  text "Top Layer - Bottom Layer" at 155.984,28.577 h1.52
  text "4" at 115.271,25.42 h1.52
  text "86.61mil (2.200mm)" at 123.704,25.42 h1.52
  text "PTH" at 139.873,25.42 h1.52
  text "Round" at 146.455,25.42 h1.52
  text "Top Layer - Bottom Layer" at 155.984,25.42 h1.52
  text "2" at 115.271,22.262 h1.52
  text "118.11mil (3.000mm)" at 123.704,22.262 h1.52
  text "PTH" at 139.873,22.262 h1.52
  text "Round" at 146.455,22.262 h1.52
  text "Top Layer - Bottom Layer" at 155.984,22.262 h1.52
  text "4" at 115.271,19.104 h1.52
  text "55.12mil (1.400mm)" at 123.704,19.104 h1.52
  text "NPTH" at 139.873,19.104 h1.52
  text "Rectangle" at 146.455,19.104 h1.52
  text "Top Layer - Bottom Layer" at 155.984,19.104 h1.52
  text "C" at 106.995,18.85 h1.4
  text "1" at 115.271,15.946 h1.52
  text "55.12mil (1.400mm)" at 123.704,15.946 h1.52
  text "PTH" at 139.873,15.946 h1.52
  text "Rectangle" at 146.455,15.946 h1.52
  text "Top Layer - Bottom Layer" at 155.984,15.946 h1.52
  text "2" at 115.271,12.789 h1.52
  text "55.12mil (1.400mm)" at 123.704,12.789 h1.52
  text "PTH" at 139.873,12.789 h1.52
  text "Rectangle" at 146.455,12.789 h1.52
  text "Top Layer - Bottom Layer" at 155.984,12.789 h1.52
  text "2" at 115.271,9.631 h1.52
  text "55.12mil (1.400mm)" at 123.704,9.631 h1.52
  text "PTH" at 139.873,9.631 h1.52
  text "Rectangle" at 146.455,9.631 h1.52
  text "Top Layer - Bottom Layer" at 155.984,9.631 h1.52
  text "2" at 115.271,6.473 h1.52
  text "55.12mil (1.400mm)" at 123.704,6.473 h1.52
  text "PTH" at 139.873,6.473 h1.52
  text "Rectangle" at 146.455,6.473 h1.52
  text "Top Layer - Bottom Layer" at 155.984,6.473 h1.52
  text "B" at 106.995,6.22 h1.4
  text "4" at 115.271,3.316 h1.52
  text "70.87mil (1.800mm)" at 123.704,3.316 h1.52
  text "PTH" at 139.873,3.316 h1.52
  text "Rectangle" at 146.455,3.316 h1.52
  text "Top Layer - Bottom Layer" at 155.984,3.316 h1.52
  text "4" at 115.271,0.158 h1.52
  text "86.61mil (2.200mm)" at 123.704,0.158 h1.52
  text "PTH" at 139.873,0.158 h1.52
  text "Rectangle" at 146.455,0.158 h1.52
  text "Top Layer - Bottom Layer" at 155.984,0.158 h1.52
  text "3" at 115.271,-3 h1.52
  text "39.37mil (1.000mm)" at 123.704,-3 h1.52
  text "PTH" at 139.873,-3 h1.52
  text "Slot" at 146.455,-3 h1.52
  text "Top Layer - Bottom Layer" at 155.984,-3 h1.52
  text "A" at 106.995,-3.254 h1.4
  text "1" at 115.271,-6.158 h1.52
  text "39.37mil (1.000mm)" at 123.704,-6.158 h1.52
  text "PTH" at 139.873,-6.158 h1.52
  text "Slot" at 146.455,-6.158 h1.52
  text "Top Layer - Bottom Layer" at 155.984,-6.158 h1.52
  text "G" at 106.995,-6.411 h1.4
  text "716 Total" at 115.271,-9.315 h1.52
  text "Slot definitions :" at 107.637,-11.526 h1.52
  text "Routed Path Length" at 119.085,-11.526 h1.52
  text "= Calculated from tool start centre position to tool end centre position." at 132.794,-11.526 h1.52
  text "Hole Length" at 119.085,-12.789 h1.52
  text "= Routed Path Length + Tool Size = Slot length as defined in the PCB layout" at 127.72,-12.789 h1.52
  text ".Layer_Name" at -20.343,-59.464 h1.52
M17 Embedded Cavity:
  text ".Layer_Name" at -20.343,-59.464 h1.52
M18 Embedded Assembly:
  text ".Layer_Name" at -20.343,-59.464 h1.52
M19 Embedded Keepout:
  text ".Layer_Name" at -20.343,-59.464 h1.52

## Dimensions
0,0 to 81.788,50 on M2 Board Dimensions
0,50 to 0,0 on M2 Board Dimensions
-34.999,-47.818 to -9.599,-47.818 on M2 Board Dimensions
